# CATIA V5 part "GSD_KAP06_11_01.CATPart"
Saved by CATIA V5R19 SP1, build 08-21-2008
Part number: GSD_BLEND_03
Definition: Beispielmodell für die Funktion Übergang / Blend.
Description: CATIA V5 Flächenmodellierung  Copyright (c) 2009 Maik Hertha IT Consultants
Bounding box of the stored display mesh (mm): x 9.925 to 49.234, y 0 to 39.794, z 0 to 65.132
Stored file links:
  C:\Users\Maik\CAD Daten\modelle\gsd_buch_uebung\GSD_KAP06_11_01.CATPart
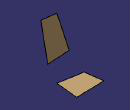
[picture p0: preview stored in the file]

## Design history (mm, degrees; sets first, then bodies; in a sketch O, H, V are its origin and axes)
AxisSystem1 "Absolute Axis System": origin (0, 0, 0), X (1, 0, 0), Y (0, 1, 0), Z (0, 0, 1)
Set1 "Planes.1"
  Plane1: type Equation, A 0, B 1, C 0, Length 0
  Plane2: type Equation, A 0, B 0, C 1, Length 0
  Plane3: type Equation, A 1, B 0, C 0, Length 0
Set2 "Skizzen.1"
  Sketch1 on Plane1, origin (0, 0, 0), H (-1, 0, 0), V (0, 0, 1)
    line L1 (-40.7892, 13.7277) -> (-49.2341, 65.1316)
    line L2 (-49.2341, 65.1316) -> (-29.5293, 63.051)
    line L3 (-29.5293, 63.051) -> (-14.1082, 15.4412)
    line L4 (-14.1082, 15.4412) -> (-40.7892, 13.7277)
  Sketch2 on Plane3, origin (0, 0, 0), H (0, 1, 0), V (0, 0, 1)
    line L1 (16.0881, 21.2572) -> (13.3955, 53.2011)
    line L2 (13.3955, 53.2011) -> (47.42, 60.6669)
    line L3 (47.42, 60.6669) -> (41.3005, 12.9347)
    line L4 (41.3005, 12.9347) -> (16.0881, 21.2572)
  Sketch3 on Plane2, origin (0, 0, 0), H (1, 0, 0), V (0, 1, 0)
    line L1 (12.7396, 17.2746) -> (9.9246, 38.9377)
    line L2 (9.9246, 38.9377) -> (44.561, 39.7944)
    line L3 (44.561, 39.7944) -> (41.746, 12.379)
    line L4 (41.746, 12.379) -> (12.7396, 17.2746)
Set3 "Basisflaechen.1"
  Split1: ToCut Plane1, Cutting Sketch1
  Split2: ToCut Plane3, Cutting Sketch2
  Split3: ToCut Plane2, Cutting Sketch3
Body1 (main body)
